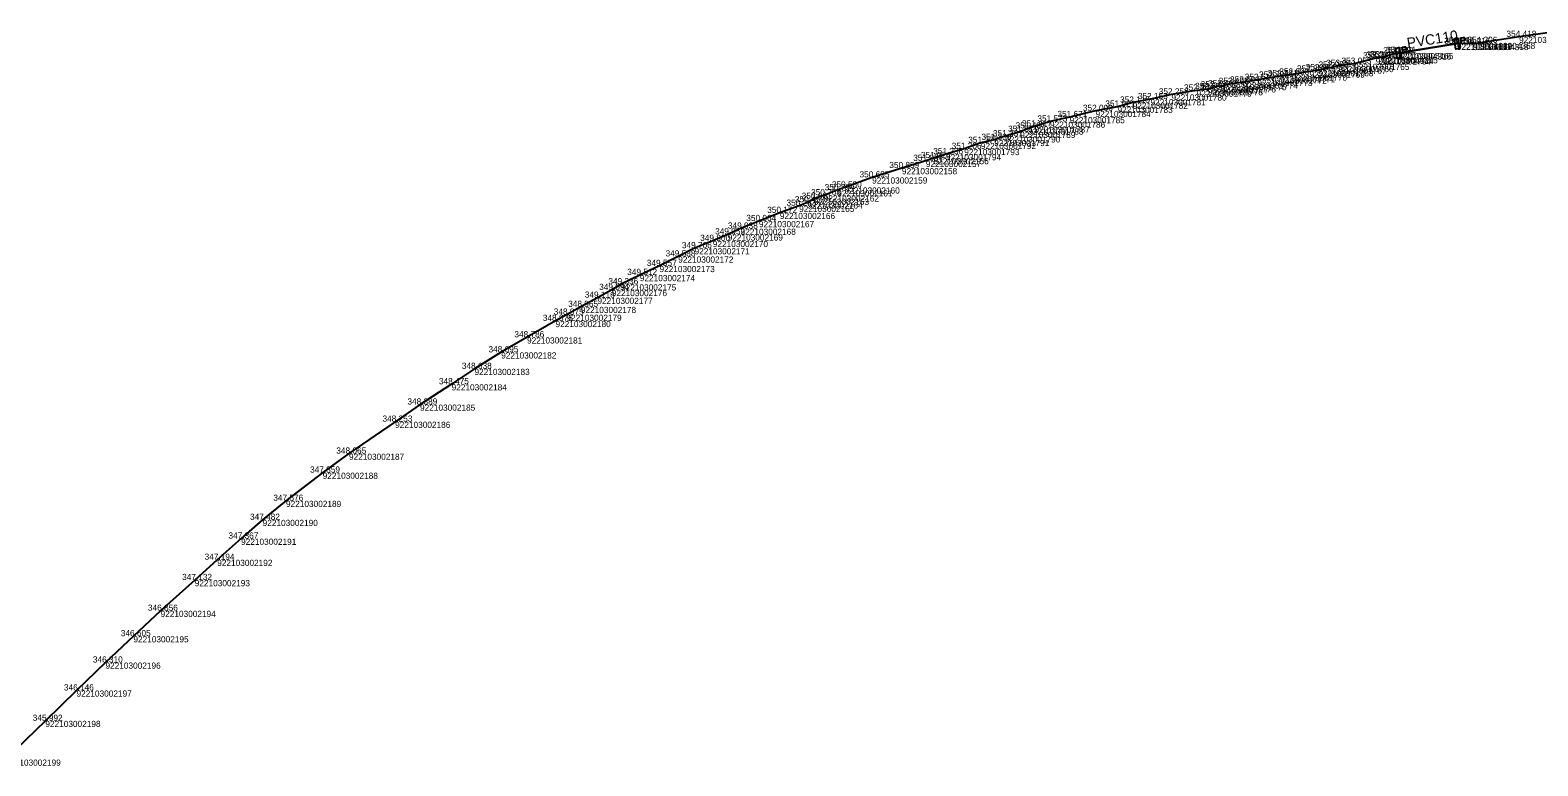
# Model space of a CAD drawing. Extents: x -771047 to -756200, y -1053876 to -1046520.
# Drawn here: x -759176.2 to -758883.8, y -1049091.4 to -1048948.7 of the extents above; entities that cross this region are included whole.
import ezdxf

# ---------------------------------------------------------------- set-up
doc = ezdxf.new("R2010")
doc.units = 0
for name, color, linetype in [('Vrstva 32', 7, 'Continuous'), ('Vrstva 33', 7, 'Continuous'), ('Vrstva 60', 7, 'Continuous'), ('Vrstva 61', 7, 'Continuous')]:
    doc.layers.add(name, color=color, linetype=linetype)

msp = doc.modelspace()

# ---------------------------------------------------------------- linework, layer by layer
at = {"layer": 'Vrstva 32'}
for points in [[(-758880.99, -1048949.1), (-758887.39, -1048949.99), (-758894.97, -1048951.16), (-758896.28, -1048951.36), (-758899.43, -1048951.3), (-758911.28, -1048953.19), (-758913.88, -1048953.92), (-758914.67, -1048954.02), (-758915.2, -1048954.15), (-758919.37, -1048955.21), (-758922.45, -1048955.63), (-758923.83, -1048955.96), (-758926.35, -1048956.44), (-758928.02, -1048956.7), (-758931.46, -1048957.3), (-758933.78, -1048957.63), (-758935.38, -1048957.88), (-758938.16, -1048958.32), (-758941.01, -1048958.83), (-758943.21, -1048959.13), (-758945.26, -1048959.57), (-758946.69, -1048959.77), (-758947.78, -1048960.11), (-758949.94, -1048960.4), (-758954.83, -1048961.15), (-758958.89, -1048962.06), (-758962.33, -1048962.75), (-758965.29, -1048963.53), (-758969.55, -1048964.35), (-758974.58, -1048965.54), (-758978.38, -1048966.41), (-758981.38, -1048967.36), (-758982.6, -1048967.75), (-758984.16, -1048968.4), (-758987.09, -1048969.28), (-758989.22, -1048969.98), (-758991.79, -1048970.56), (-758995.01, -1048971.73), (-758998.57, -1048972.75), (-759000.97, -1048973.5), (-759002.46, -1048974.04), (-759007.1, -1048975.44), (-759012.88, -1048977.25), (-759018.24, -1048979.19), (-759019.64, -1048979.75)], [(-759019.64, -1048979.75), (-759022.27, -1048980.73), (-759024.2, -1048981.4), (-759025.43, -1048982.09)], [(-759025.43, -1048982.09), (-759027.04, -1048982.75), (-759030.78, -1048984.13), (-759034.84, -1048985.71), (-759038.4, -1048987.19), (-759040.9, -1048988.3), (-759043.79, -1048989.57), (-759047.33, -1048990.98), (-759050.5, -1048992.58), (-759054.13, -1048994.43), (-759057.94, -1048996.18), (-759061.59, -1048997.98), (-759063.38, -1048999.08), (-759066.17, -1049000.59), (-759069.38, -1049002.36), (-759072.18, -1049003.88), (-759074.3, -1049005.09), (-759079.82, -1049008.27), (-759084.84, -1049011.18), (-759090.02, -1049014.39), (-759094.45, -1049017.37), (-759100.58, -1049021.31), (-759105.41, -1049024.64), (-759114.36, -1049030.83), (-759119.46, -1049034.52), (-759126.58, -1049039.98), (-759131.11, -1049043.67), (-759135.29, -1049047.32), (-759139.92, -1049051.42), (-759144.28, -1049055.35), (-759150.91, -1049061.31), (-759156.18, -1049066.24), (-759161.6, -1049071.35), (-759167.21, -1049076.77), (-759173.26, -1049082.66), (-759180.98, -1049090.17)]]:
    msp.add_lwpolyline(points, dxfattribs=at)
at = {"layer": 'Vrstva 33'}
for points in [[(-758900, -1048950.38), (-758899.26, -1048950.26), (-758898.95, -1048952.25), (-758899.68, -1048952.37)], [(-758911.35, -1048952.17), (-758910.62, -1048952.05), (-758910.3, -1048954.04), (-758911.03, -1048954.16)]]:
    msp.add_lwpolyline(points, close=True, dxfattribs=at)
for points in [[(-758898.75, -1048950.18), (-758898.23, -1048950.09)], [(-758898.55, -1048951.41), (-758898.75, -1048950.18)], [(-758898.23, -1048950.09), (-758898.07, -1048950.12), (-758897.93, -1048950.3), (-758897.91, -1048950.41), (-758897.99, -1048950.64), (-758898.14, -1048950.71)], [(-758911.28, -1048953.19), (-758899.43, -1048951.3)], [(-758910.1, -1048951.97), (-758909.59, -1048951.89)], [(-758909.9, -1048953.21), (-758910.1, -1048951.97)], [(-758909.49, -1048952.5), (-758910, -1048952.58)], [(-758909.59, -1048951.89), (-758909.42, -1048951.91), (-758909.28, -1048952.1), (-758909.26, -1048952.2), (-758909.34, -1048952.43), (-758909.49, -1048952.5)], [(-758898.14, -1048950.71), (-758898.65, -1048950.79)]]:
    msp.add_lwpolyline(points, dxfattribs=at)
at = {"layer": 'Vrstva 60'}
for p, q in [((-758887.39, -1048949.99), (-758887.39, -1048949.99)), ((-758911.28, -1048953.19), (-758911.28, -1048953.19)), ((-758910.82, -1048953.11), (-758910.82, -1048953.11)), ((-758899.47, -1048951.32), (-758899.47, -1048951.32)), ((-758899.43, -1048951.3), (-758899.43, -1048951.3)), ((-758896.28, -1048951.36), (-758896.28, -1048951.36)), ((-758894.97, -1048951.16), (-758894.97, -1048951.16)), ((-758923.83, -1048955.96), (-758923.83, -1048955.96)), ((-758922.45, -1048955.63), (-758922.45, -1048955.63)), ((-758919.37, -1048955.21), (-758919.37, -1048955.21)), ((-758915.2, -1048954.15), (-758915.2, -1048954.15)), ((-758914.67, -1048954.02), (-758914.67, -1048954.02)), ((-758913.88, -1048953.92), (-758913.88, -1048953.92)), ((-758943.21, -1048959.13), (-758943.21, -1048959.13)), ((-758941.01, -1048958.83), (-758941.01, -1048958.83)), ((-758938.16, -1048958.32), (-758938.16, -1048958.32)), ((-758935.38, -1048957.88), (-758935.38, -1048957.88)), ((-758933.78, -1048957.63), (-758933.78, -1048957.63)), ((-758931.46, -1048957.3), (-758931.46, -1048957.3)), ((-758928.02, -1048956.7), (-758928.02, -1048956.7)), ((-758926.35, -1048956.44), (-758926.35, -1048956.44)), ((-758958.89, -1048962.06), (-758958.89, -1048962.06)), ((-758954.83, -1048961.15), (-758954.83, -1048961.15)), ((-758949.94, -1048960.4), (-758949.94, -1048960.4)), ((-758947.78, -1048960.11), (-758947.78, -1048960.11)), ((-758946.69, -1048959.77), (-758946.69, -1048959.77)), ((-758945.26, -1048959.57), (-758945.26, -1048959.57)), ((-758969.55, -1048964.35), (-758969.55, -1048964.35)), ((-758965.29, -1048963.53), (-758965.29, -1048963.53)), ((-758962.33, -1048962.75), (-758962.33, -1048962.75)), ((-758982.6, -1048967.75), (-758982.6, -1048967.75)), ((-758981.38, -1048967.36), (-758981.38, -1048967.36)), ((-758978.38, -1048966.41), (-758978.38, -1048966.41)), ((-758974.58, -1048965.54), (-758974.58, -1048965.54)), ((-758991.79, -1048970.56), (-758991.79, -1048970.56)), ((-758989.22, -1048969.98), (-758989.22, -1048969.98)), ((-758987.09, -1048969.28), (-758987.09, -1048969.28)), ((-758984.16, -1048968.4), (-758984.16, -1048968.4)), ((-759000.97, -1048973.5), (-759000.97, -1048973.5)), ((-758998.57, -1048972.75), (-758998.57, -1048972.75)), ((-758995.01, -1048971.73), (-758995.01, -1048971.73)), ((-759007.1, -1048975.44), (-759007.1, -1048975.44)), ((-759002.46, -1048974.04), (-759002.46, -1048974.04)), ((-759019.64, -1048979.75), (-759019.64, -1048979.75)), ((-759018.24, -1048979.19), (-759018.24, -1048979.19)), ((-759012.88, -1048977.25), (-759012.88, -1048977.25)), ((-759025.43, -1048982.09), (-759025.43, -1048982.09)), ((-759024.2, -1048981.4), (-759024.2, -1048981.4)), ((-759022.27, -1048980.73), (-759022.27, -1048980.73)), ((-759030.78, -1048984.13), (-759030.78, -1048984.13)), ((-759027.04, -1048982.75), (-759027.04, -1048982.75)), ((-759040.9, -1048988.3), (-759040.9, -1048988.3)), ((-759038.4, -1048987.19), (-759038.4, -1048987.19)), ((-759034.84, -1048985.71), (-759034.84, -1048985.71)), ((-759047.33, -1048990.98), (-759047.33, -1048990.98)), ((-759043.79, -1048989.57), (-759043.79, -1048989.57)), ((-759050.5, -1048992.58), (-759050.5, -1048992.58)), ((-759057.94, -1048996.18), (-759057.94, -1048996.18)), ((-759054.13, -1048994.43), (-759054.13, -1048994.43)), ((-759063.38, -1048999.08), (-759063.38, -1048999.08)), ((-759061.59, -1048997.98), (-759061.59, -1048997.98)), ((-759069.38, -1049002.36), (-759069.38, -1049002.36)), ((-759066.17, -1049000.59), (-759066.17, -1049000.59)), ((-759074.3, -1049005.09), (-759074.3, -1049005.09)), ((-759072.18, -1049003.88), (-759072.18, -1049003.88)), ((-759079.82, -1049008.27), (-759079.82, -1049008.27)), ((-759084.84, -1049011.18), (-759084.84, -1049011.18)), ((-759090.02, -1049014.39), (-759090.02, -1049014.39)), ((-759094.45, -1049017.37), (-759094.45, -1049017.37)), ((-759100.58, -1049021.31), (-759100.58, -1049021.31)), ((-759105.41, -1049024.64), (-759105.41, -1049024.64)), ((-759114.36, -1049030.83), (-759114.36, -1049030.83)), ((-759119.46, -1049034.52), (-759119.46, -1049034.52)), ((-759126.58, -1049039.98), (-759126.58, -1049039.98)), ((-759131.11, -1049043.67), (-759131.11, -1049043.67)), ((-759135.29, -1049047.32), (-759135.29, -1049047.32)), ((-759139.92, -1049051.42), (-759139.92, -1049051.42)), ((-759144.28, -1049055.35), (-759144.28, -1049055.35)), ((-759150.91, -1049061.31), (-759150.91, -1049061.31)), ((-759156.18, -1049066.24), (-759156.18, -1049066.24)), ((-759161.6, -1049071.35), (-759161.6, -1049071.35)), ((-759167.21, -1049076.77), (-759167.21, -1049076.77)), ((-759173.26, -1049082.66), (-759173.26, -1049082.66))]:
    msp.add_line(p, q, dxfattribs=at)

# ---------------------------------------------------------------- texts
at = {"layer": 'Vrstva 33'}
msp.add_text('PVC110', height=2, rotation=9.0654, dxfattribs=at).set_placement((-758908.98, -1048952.2))
at = {"layer": 'Vrstva 60'}
for s, p in [('922103004367', (-758887.39, -1048951.19)), ('922103004316', (-758911.28, -1048954.39)), ('922103005165', (-758910.82, -1048954.31)), ('922103005166', (-758899.47, -1048952.52)), ('922103004317', (-758899.43, -1048952.5)), ('922103004318', (-758896.28, -1048952.56)), ('922103004368', (-758894.97, -1048952.35)), ('922103001767', (-758923.83, -1048957.16)), ('922103001766', (-758922.45, -1048956.83)), ('922103001765', (-758919.37, -1048956.41)), ('922103001764', (-758915.2, -1048955.35)), ('922103004314', (-758914.67, -1048955.22)), ('922103004315', (-758913.88, -1048955.12)), ('922103001775', (-758943.21, -1048960.33)), ('922103001774', (-758941.01, -1048960.03)), ('922103001773', (-758938.16, -1048959.52)), ('922103001772', (-758935.38, -1048959.08)), ('922103001771', (-758933.78, -1048958.83)), ('922103001770', (-758931.46, -1048958.5)), ('922103001769', (-758928.02, -1048957.9)), ('922103001768', (-758926.35, -1048957.64)), ('922103001781', (-758958.89, -1048963.27)), ('922103001780', (-758954.83, -1048962.35)), ('922103001779', (-758949.94, -1048961.6)), ('922103001778', (-758947.78, -1048961.31)), ('922103001777', (-758946.69, -1048960.97)), ('922103001776', (-758945.26, -1048960.77)), ('922103001784', (-758969.55, -1048965.55)), ('922103001783', (-758965.29, -1048964.73)), ('922103001782', (-758962.33, -1048963.95)), ('922103001788', (-758982.6, -1048968.95)), ('922103001787', (-758981.38, -1048968.56)), ('922103001786', (-758978.38, -1048967.61)), ('922103001785', (-758974.58, -1048966.74)), ('922103001792', (-758991.79, -1048971.76)), ('922103001791', (-758989.22, -1048971.18)), ('922103001790', (-758987.09, -1048970.48)), ('922103001789', (-758984.16, -1048969.6)), ('922103002156', (-759000.97, -1048974.7)), ('922103001794', (-758998.57, -1048973.95)), ('922103001793', (-758995.01, -1048972.93)), ('922103002158', (-759007.1, -1048976.64)), ('922103002157', (-759002.46, -1048975.24)), ('922103002161', (-759019.64, -1048980.95)), ('922103002160', (-759018.24, -1048980.39)), ('922103002159', (-759012.88, -1048978.45)), ('922103002164', (-759025.43, -1048983.29)), ('922103002163', (-759024.2, -1048982.6)), ('922103002162', (-759022.27, -1048981.93)), ('922103002166', (-759030.78, -1048985.33)), ('922103002165', (-759027.04, -1048983.95)), ('922103002169', (-759040.9, -1048989.5)), ('922103002168', (-759038.4, -1048988.39)), ('922103002167', (-759034.84, -1048986.91)), ('922103002171', (-759047.33, -1048992.18)), ('922103002170', (-759043.79, -1048990.77)), ('922103002173', (-759054.13, -1048995.62)), ('922103002172', (-759050.5, -1048993.78)), ('922103002174', (-759057.94, -1048997.38)), ('922103002176', (-759063.38, -1049000.28)), ('922103002175', (-759061.59, -1048999.18)), ('922103002178', (-759069.38, -1049003.56)), ('922103002177', (-759066.17, -1049001.79)), ('922103002180', (-759074.3, -1049006.29)), ('922103002179', (-759072.18, -1049005.08)), ('922103002181', (-759079.82, -1049009.47)), ('922103002182', (-759084.84, -1049012.38)), ('922103002183', (-759090.02, -1049015.58)), ('922103002184', (-759094.45, -1049018.57)), ('922103002185', (-759100.58, -1049022.51)), ('922103002186', (-759105.41, -1049025.84)), ('922103002187', (-759114.36, -1049032.03)), ('922103002188', (-759119.46, -1049035.72)), ('922103002189', (-759126.58, -1049041.18)), ('922103002190', (-759131.11, -1049044.87)), ('922103002191', (-759135.29, -1049048.52)), ('922103002192', (-759139.92, -1049052.62)), ('922103002193', (-759144.28, -1049056.55)), ('922103002194', (-759150.91, -1049062.51)), ('922103002195', (-759156.18, -1049067.44)), ('922103002196', (-759161.6, -1049072.55)), ('922103002197', (-759167.21, -1049077.97)), ('922103002198', (-759173.26, -1049083.86)), ('922103002199', (-759180.98, -1049091.37))]:
    msp.add_text(s, height=1.2, dxfattribs=at).set_placement(p)
at = {"layer": 'Vrstva 61'}
for s, p in [('354.996', (-758901.92, -1048951.32)), ('353.816', (-758901.88, -1048951.3)), ('354.215', (-758898.73, -1048951.36)), ('354.206', (-758897.42, -1048951.16)), ('354.418', (-758889.84, -1048949.99)), ('353.247', (-758917.65, -1048954.15)), ('353.611', (-758917.02, -1048954.02)), ('353.417', (-758916.33, -1048953.92)), ('353.539', (-758913.74, -1048953.19)), ('354.991', (-758913.18, -1048953.11)), ('352.893', (-758933.91, -1048957.3)), ('352.869', (-758930.48, -1048956.7)), ('352.954', (-758928.8, -1048956.44)), ('352.953', (-758926.29, -1048955.96)), ('353.041', (-758924.81, -1048955.63)), ('353.053', (-758921.83, -1048955.21)), ('352.304', (-758952.39, -1048960.4)), ('352.390', (-758950.23, -1048960.11)), ('352.437', (-758949.14, -1048959.77)), ('352.462', (-758947.71, -1048959.57)), ('352.495', (-758945.66, -1048959.13)), ('352.604', (-758943.46, -1048958.83)), ('352.610', (-758940.61, -1048958.32)), ('352.708', (-758937.83, -1048957.88)), ('352.781', (-758936.14, -1048957.63)), ('352.115', (-758964.79, -1048962.75)), ('352.153', (-758961.34, -1048962.06)), ('352.258', (-758957.28, -1048961.15)), ('351.671', (-758976.94, -1048965.54)), ('352.006', (-758972, -1048964.35)), ('351.921', (-758967.65, -1048963.53)), ('351.331', (-758989.45, -1048969.28)), ('351.511', (-758986.52, -1048968.4)), ('351.497', (-758985.05, -1048967.75)), ('351.417', (-758983.83, -1048967.36)), ('351.573', (-758980.83, -1048966.41)), ('351.206', (-758997.46, -1048971.73)), ('351.277', (-758994.24, -1048970.56)), ('351.336', (-758991.67, -1048969.98)), ('351.057', (-759004.91, -1048974.04)), ('351.024', (-759003.42, -1048973.5)), ('351.236', (-759001.03, -1048972.75)), ('350.695', (-759015.33, -1048977.25)), ('350.859', (-759009.55, -1048975.44)), ('350.708', (-759024.72, -1048980.73)), ('350.794', (-759022.09, -1048979.75)), ('350.580', (-759020.7, -1048979.19)), ('350.243', (-759029.5, -1048982.75)), ('350.453', (-759027.88, -1048982.09)), ('350.661', (-759026.55, -1048981.4)), ('350.064', (-759037.29, -1048985.71)), ('350.172', (-759033.23, -1048984.13)), ('349.800', (-759046.24, -1048989.57)), ('349.952', (-759043.34, -1048988.3)), ('349.938', (-759040.86, -1048987.19)), ('349.588', (-759052.95, -1048992.58)), ('349.706', (-759049.79, -1048990.98)), ('349.557', (-759056.59, -1048994.43)), ('349.336', (-759064.05, -1048997.98)), ('349.512', (-759060.39, -1048996.18)), ('349.116', (-759068.62, -1049000.59)), ('349.094', (-759065.83, -1048999.08)), ('348.975', (-759074.64, -1049003.88)), ('348.965', (-759071.84, -1049002.36)), ('348.876', (-759076.76, -1049005.09)), ('348.786', (-759082.28, -1049008.27)), ('348.695', (-759087.3, -1049011.18)), ('348.638', (-759092.47, -1049014.39)), ('348.475', (-759096.91, -1049017.37)), ('348.389', (-759103.03, -1049021.31)), ('348.253', (-759107.86, -1049024.64)), ('348.065', (-759116.82, -1049030.83)), ('347.859', (-759121.91, -1049034.52)), ('347.576', (-759129.04, -1049039.98)), ('347.482', (-759133.56, -1049043.67)), ('347.367', (-759137.74, -1049047.32)), ('347.194', (-759142.37, -1049051.42)), ('347.132', (-759146.73, -1049055.35)), ('346.856', (-759153.36, -1049061.31)), ('346.605', (-759158.63, -1049066.24)), ('346.310', (-759164.05, -1049071.35)), ('346.146', (-759169.66, -1049076.77)), ('345.992', (-759175.71, -1049082.66))]:
    msp.add_text(s, height=1.2, dxfattribs=at).set_placement(p)

doc.saveas('drawing.dxf')
